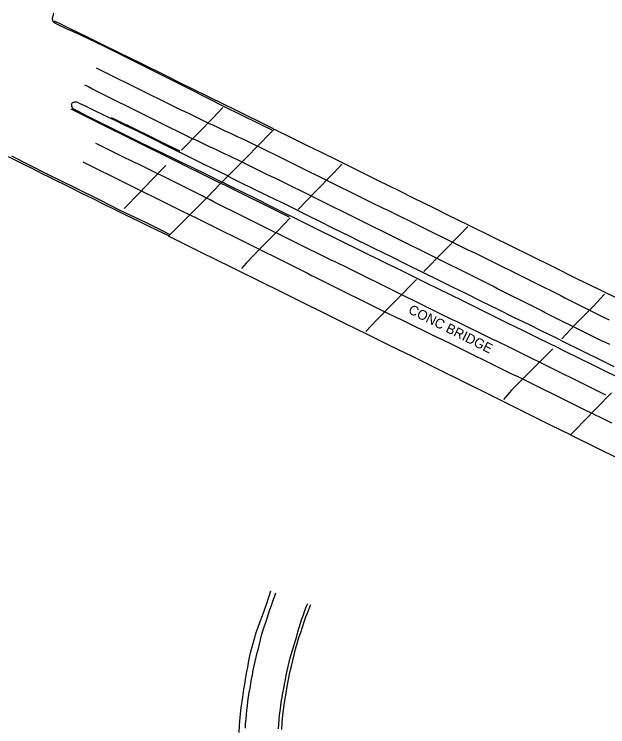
# Model space of a CAD drawing. Extents: x 1961683 to 1977751, y 798292 to 805767.
# Drawn here: x 1963000.6 to 1963330.2, y 799570.9 to 799966.6 of the extents above; entities that cross this region are included whole.
import ezdxf

# ---------------------------------------------------------------- set-up
doc = ezdxf.new("R2010")
doc.units = 0
for name, color, linetype in [('RD_EX_Bridge', 7, 'Continuous'), ('RD_EX_Bridge_Seam', 7, 'Continuous'), ('RD_EX_Conc', 7, 'Continuous'), ('RD_EX_Road', 7, 'Continuous'), ('RD_EX_Road_Paint', 7, 'Continuous'), ('RD_TX_RoadID', 7, 'Continuous')]:
    doc.layers.add(name, color=color, linetype=linetype)

msp = doc.modelspace()

# ---------------------------------------------------------------- linework, layer by layer
at = {"layer": 'RD_EX_Bridge'}
msp.add_lwpolyline([(1963332.27, 799756.44), (1963323.69, 799747.66), (1963317.32, 799741.08), (1963312.27, 799735.9), (1963309.4, 799732.97), (1963298.46, 799738.5), (1963282.11, 799746.62), (1963263.88, 799755.63), (1963250.13, 799762.41), (1963236.95, 799768.9), (1963222.78, 799775.95), (1963208.59, 799782.91), (1963196.82, 799788.73), (1963183.78, 799795.09), (1963172.38, 799800.78), (1963161.33, 799806.22), (1963149.22, 799812.21), (1963137.46, 799817.94), (1963121.48, 799825.98), (1963104.02, 799834.57), (1963086.31, 799843.33), (1963089.07, 799846.09), (1963098.17, 799855.18), (1963107.97, 799865.03), (1963114.7, 799872.23), (1963120.17, 799877.62), (1963129.42, 799886.96), (1963136.21, 799893.91), (1963143.07, 799900.86), (1963145, 799902.81), (1963154.36, 799898.23), (1963162.56, 799894.13), (1963170.65, 799890.17), (1963180.48, 799885.35), (1963191.19, 799879.95), (1963202.67, 799874.28), (1963214.45, 799868.55), (1963222.05, 799864.74), (1963233.51, 799859.13), (1963241.24, 799855.29), (1963252.64, 799849.67), (1963265.45, 799843.36), (1963276.64, 799837.85), (1963287.24, 799832.62), (1963300.11, 799826.32), (1963312.87, 799819.96), (1963325.6, 799813.75), (1963336.46, 799808.32)], dxfattribs=at)
at = {"layer": 'RD_EX_Bridge_Seam'}
for points in [[(1963158.28, 799858.15), (1963167.38, 799867.61), (1963178.01, 799878.63), (1963182.5, 799883.4)], [(1963153.87, 799853.49), (1963146.81, 799846.24), (1963137.2, 799836.5), (1963129.34, 799828.39), (1963126.78, 799825.34)], [(1963228.04, 799823.72), (1963238.72, 799834.71), (1963248.05, 799844.19), (1963252.46, 799848.75)], [(1963223.95, 799819.31), (1963212.48, 799807.62), (1963201.95, 799796.9), (1963195.93, 799790.51)], [(1963304.68, 799786.45), (1963311.96, 799794.09), (1963322.11, 799804.4), (1963328.44, 799811.09)], [(1963299.59, 799780.86), (1963286.57, 799767.73), (1963276.73, 799757.77), (1963272.28, 799752.71)]]:
    msp.add_lwpolyline(points, dxfattribs=at)
at = {"layer": 'RD_EX_Conc'}
for points in [[(1963119.13, 799876.82), (1963114.15, 799879.27), (1963106.16, 799883.21), (1963100.49, 799886.04), (1963095.38, 799888.57), (1963090.42, 799891), (1963084.86, 799893.77), (1963078.25, 799897.08), (1963073.87, 799899.24), (1963068.65, 799901.79), (1963062.6, 799904.72), (1963056.61, 799907.61), (1963051.55, 799910.05), (1963044.26, 799913.56), (1963039.79, 799915.71), (1963037.23, 799916.96), (1963035.86, 799917.58), (1963035.35, 799917.76), (1963034.96, 799917.85), (1963034.63, 799917.87), (1963034.29, 799917.85), (1963033.94, 799917.8), (1963033.59, 799917.7), (1963033.25, 799917.58), (1963032.96, 799917.44), (1963032.73, 799917.27), (1963032.54, 799917.09), (1963032.4, 799916.89), (1963032.33, 799916.68), (1963032.3, 799916.47), (1963032.33, 799916.25), (1963032.46, 799915.77), (1963032.62, 799915.25), (1963032.71, 799914.98), (1963032.84, 799914.75), (1963033.01, 799914.55), (1963033.2, 799914.37), (1963034.33, 799913.7), (1963036.84, 799912.36), (1963040.13, 799910.66), (1963043.57, 799908.93), (1963047.66, 799906.89), (1963052.9, 799904.27), (1963058.48, 799901.48), (1963063.62, 799898.95), (1963069.31, 799896.17), (1963076.54, 799892.63), (1963083.42, 799889.29), (1963088.04, 799887.09), (1963092.6, 799884.92), (1963099.28, 799881.68), (1963107.27, 799877.76), (1963115.75, 799873.58)], [(1963093.58, 799891.12), (1963103.07, 799900.87), (1963110.66, 799908.8), (1963116.49, 799914.89)], [(1963061.57, 799858.83), (1963070.28, 799867.67), (1963076.55, 799874.05), (1963084.73, 799882.55)], [(1963119.38, 799876.69), (1963121.88, 799875.43), (1963126.34, 799873.22), (1963132.75, 799870.08), (1963141.1, 799866.02), (1963145.77, 799863.74), (1963150.48, 799861.43), (1963155.22, 799859.08), (1963160, 799856.69), (1963164.73, 799854.32), (1963169.32, 799852.03), (1963178.11, 799847.65), (1963186.9, 799843.31), (1963191.5, 799841.05), (1963196.22, 799838.73), (1963200.94, 799836.42), (1963209.88, 799832.02), (1963218.29, 799827.85), (1963226.89, 799823.62), (1963235.68, 799819.33), (1963243.87, 799815.3), (1963251.55, 799811.5), (1963259.95, 799807.34), (1963264.49, 799805.09), (1963269.09, 799802.82), (1963277.9, 799798.48), (1963286.14, 799794.44), (1963293.41, 799790.87), (1963300, 799787.62), (1963308.03, 799783.64), (1963312.72, 799781.32), (1963317.49, 799778.97), (1963326.11, 799774.71), (1963333.52, 799771.06)], [(1963334.46, 799765.62), (1963328.66, 799768.46), (1963321.67, 799771.89), (1963313.68, 799775.83), (1963306.48, 799779.4), (1963301.84, 799781.68), (1963297.6, 799783.75), (1963291.58, 799786.7), (1963283.76, 799790.54), (1963279.16, 799792.81), (1963274.1, 799795.31), (1963268.61, 799798.02), (1963262.7, 799800.94), (1963256.37, 799804.07), (1963249.62, 799807.39), (1963242.83, 799810.74), (1963236.36, 799813.93), (1963230.22, 799816.96), (1963224.41, 799819.82), (1963218.78, 799822.59), (1963213.19, 799825.34), (1963207.64, 799828.06), (1963202.14, 799830.76), (1963196.48, 799833.55), (1963190.46, 799836.52), (1963184.08, 799839.68), (1963177.33, 799843.03), (1963170.88, 799846.23), (1963165.38, 799848.95), (1963157.24, 799852.97), (1963150.62, 799856.23), (1963143.22, 799859.92), (1963135.36, 799863.84), (1963127.34, 799867.84), (1963120.58, 799871.19), (1963116.52, 799873.2), (1963116.12, 799873.4)]]:
    msp.add_lwpolyline(points, dxfattribs=at)
at = {"layer": 'RD_EX_Road'}
for points in [[(1963022.38, 799967.3), (1963022.15, 799966.43), (1963021.96, 799965.64), (1963021.81, 799964.92), (1963021.74, 799964.38), (1963021.73, 799964.19), (1963021.74, 799964), (1963021.81, 799963.57), (1963021.93, 799963.07), (1963022, 799962.86), (1963022.09, 799962.69), (1963022.19, 799962.56), (1963022.38, 799962.42), (1963023.24, 799961.9), (1963024.55, 799961.2), (1963029.85, 799958.58), (1963032.94, 799957.16), (1963041, 799953.45), (1963050.5, 799948.9), (1963059.48, 799944.45), (1963068.35, 799940.02), (1963078.35, 799935.05), (1963088.66, 799929.83), (1963098.65, 799924.86), (1963107.81, 799920.27), (1963117.47, 799915.27), (1963125.89, 799911.14), (1963137.26, 799905.5), (1963143.63, 799902.39)], [(1963022.71, 799963), (1963023.11, 799962.84), (1963025.87, 799961.42), (1963030.66, 799959.11), (1963041.8, 799953.71), (1963049.3, 799949.96), (1963059.13, 799945.2), (1963070.89, 799939.38), (1963085.09, 799932.34), (1963092.31, 799928.7), (1963107.53, 799921.27), (1963117.83, 799916.23), (1963122, 799914.21), (1963144.45, 799903.09)], [(1962997.32, 799887.53), (1963001.34, 799885.57), (1963006.15, 799883.18), (1963011.05, 799880.71), (1963015.89, 799878.26), (1963020.27, 799876.06), (1963024.19, 799874.1), (1963028.11, 799872.18), (1963032.26, 799870.17), (1963037.69, 799867.51), (1963044.3, 799864.23), (1963050.44, 799861.15), (1963056.03, 799858.32), (1963062.37, 799855.23), (1963069.89, 799851.65), (1963074.62, 799849.37), (1963080.06, 799846.72), (1963086.22, 799843.69)], [(1963086.85, 799844.36), (1963082.23, 799846.78), (1963073.61, 799851.02), (1963059.03, 799857.89), (1963048.29, 799863.38), (1963034.5, 799870.2), (1963026.55, 799874.03), (1963018.86, 799877.88), (1963009.05, 799882.85), (1962999.21, 799887.76)], [(1963309.51, 799733.08), (1963336.93, 799719.62)], [(1963142.99, 799646.2), (1963142.2, 799643.88), (1963141.44, 799641.51), (1963140.72, 799639.24), (1963140.01, 799637.17), (1963139.26, 799635.2), (1963138.24, 799632.56), (1963136.98, 799629.25), (1963135.81, 799626.06), (1963134.78, 799623.03), (1963133.78, 799619.81), (1963132.84, 799616.46), (1963132.14, 799613.84), (1963131.67, 799611.88), (1963131.15, 799609.46), (1963130.57, 799606.54), (1963130.06, 799603.9), (1963129.65, 799601.62), (1963129.27, 799599.38), (1963128.9, 799597.1), (1963128.47, 799594.62), (1963127.95, 799591.73), (1963127.28, 799587.31), (1963126.5, 799581.49), (1963125.92, 799576.18), (1963125.57, 799571.68), (1963125.33, 799567.81)], [(1963149.12, 799569.41), (1963149.43, 799573.25), (1963149.84, 799577.42), (1963150.33, 799581.55), (1963150.9, 799585.59), (1963151.54, 799589.49), (1963152.24, 799593.34), (1963152.97, 799597.25), (1963153.73, 799601.03), (1963154.5, 799604.52), (1963155.27, 799607.78), (1963156.04, 799610.88), (1963156.85, 799613.99), (1963157.76, 799617.25), (1963158.72, 799620.43), (1963159.66, 799623.32), (1963160.63, 799626.17), (1963161.67, 799629.2), (1963162.61, 799631.9), (1963163.3, 799633.71), (1963164.01, 799635.48), (1963165.01, 799638.04), (1963165.34, 799638.85)]]:
    msp.add_lwpolyline(points, dxfattribs=at)
at = {"layer": 'RD_EX_Road_Paint'}
for points in [[(1963046.07, 799936.78), (1963048.31, 799935.67), (1963050.55, 799934.57), (1963052.8, 799933.46), (1963055.04, 799932.36), (1963057.28, 799931.25), (1963059.52, 799930.15), (1963061.76, 799929.04), (1963064.01, 799927.94), (1963066.25, 799926.83), (1963068.49, 799925.73), (1963070.73, 799924.62), (1963072.98, 799923.52), (1963075.22, 799922.42), (1963077.47, 799921.32), (1963079.71, 799920.22), (1963081.96, 799919.12), (1963084.2, 799918.02), (1963086.45, 799916.92), (1963088.69, 799915.82), (1963090.94, 799914.72), (1963093.18, 799913.62), (1963095.43, 799912.52), (1963097.67, 799911.42), (1963099.92, 799910.32), (1963102.16, 799909.22), (1963104.41, 799908.12), (1963106.66, 799907.04), (1963108.92, 799905.98), (1963111.19, 799904.93), (1963113.46, 799903.87), (1963115.72, 799902.81), (1963117.99, 799901.76), (1963120.25, 799900.7), (1963122.52, 799899.64), (1963124.78, 799898.58), (1963127.05, 799897.53), (1963129.31, 799896.47), (1963131.58, 799895.41), (1963133.82, 799894.31), (1963135.41, 799893.52)], [(1963126.76, 799884.62), (1963124.51, 799885.71), (1963122.26, 799886.81), (1963120.02, 799887.91), (1963117.77, 799889), (1963115.51, 799890.07), (1963113.25, 799891.13), (1963110.98, 799892.19), (1963108.72, 799893.26), (1963106.46, 799894.32), (1963104.2, 799895.38), (1963101.93, 799896.44), (1963099.67, 799897.51), (1963097.41, 799898.57), (1963095.14, 799899.63), (1963092.88, 799900.7), (1963090.63, 799901.79), (1963088.4, 799902.91), (1963086.16, 799904.03), (1963083.93, 799905.15), (1963081.69, 799906.27), (1963079.46, 799907.39), (1963077.22, 799908.5), (1963074.99, 799909.62), (1963072.75, 799910.74), (1963070.52, 799911.86), (1963068.28, 799912.98), (1963066.05, 799914.1), (1963063.81, 799915.22), (1963061.58, 799916.34), (1963059.34, 799917.46), (1963057.11, 799918.58), (1963054.87, 799919.7), (1963052.64, 799920.82), (1963050.4, 799921.94), (1963048.17, 799923.06), (1963045.93, 799924.18), (1963043.7, 799925.29), (1963041.46, 799926.41), (1963039.85, 799927.22)], [(1963115.01, 799872.87), (1963112.77, 799873.98), (1963110.53, 799875.09), (1963108.29, 799876.19), (1963106.04, 799877.3), (1963103.8, 799878.41), (1963101.56, 799879.51), (1963099.32, 799880.62), (1963097.08, 799881.73), (1963094.84, 799882.84), (1963092.6, 799883.94), (1963090.36, 799885.05), (1963088.11, 799886.16), (1963085.87, 799887.26), (1963083.63, 799888.37), (1963081.39, 799889.48), (1963079.15, 799890.58), (1963076.91, 799891.69), (1963074.67, 799892.8), (1963072.42, 799893.9), (1963070.18, 799895.01), (1963067.94, 799896.12), (1963065.7, 799897.23), (1963063.46, 799898.34), (1963061.22, 799899.45), (1963058.99, 799900.57), (1963056.75, 799901.68), (1963054.51, 799902.8), (1963052.27, 799903.91), (1963050.04, 799905.02), (1963047.8, 799906.14), (1963045.56, 799907.25), (1963043.32, 799908.37), (1963041.09, 799909.48), (1963038.85, 799910.6), (1963036.61, 799911.71), (1963034.37, 799912.82), (1963032.18, 799913.92)], [(1963054.53, 799909.33), (1963056.78, 799908.23), (1963059.02, 799907.13), (1963061.27, 799906.04), (1963063.51, 799904.94), (1963065.76, 799903.84), (1963068.01, 799902.74), (1963070.25, 799901.64), (1963072.5, 799900.55), (1963074.74, 799899.45), (1963076.99, 799898.35), (1963079.23, 799897.25), (1963081.48, 799896.15), (1963083.73, 799895.06), (1963085.97, 799893.96), (1963088.22, 799892.86), (1963090.46, 799891.76), (1963092.49, 799890.77)], [(1963107.28, 799864.56), (1963105.04, 799865.69), (1963102.81, 799866.81), (1963100.58, 799867.93), (1963098.34, 799869.05), (1963096.11, 799870.18), (1963093.87, 799871.3), (1963091.64, 799872.42), (1963089.41, 799873.54), (1963087.16, 799874.64), (1963084.92, 799875.75), (1963082.67, 799876.85), (1963080.43, 799877.95), (1963078.19, 799879.05), (1963075.94, 799880.16), (1963073.7, 799881.26), (1963071.46, 799882.36), (1963069.21, 799883.46), (1963066.97, 799884.56), (1963064.73, 799885.67), (1963062.48, 799886.77), (1963060.24, 799887.87), (1963057.99, 799888.97), (1963055.75, 799890.07), (1963053.51, 799891.18), (1963051.26, 799892.28), (1963049.02, 799893.38), (1963046.78, 799894.48), (1963045.97, 799894.88)], [(1963135.9, 799893.28), (1963138.14, 799892.17), (1963140.38, 799891.06), (1963142.62, 799889.95), (1963144.86, 799888.84), (1963147.1, 799887.73), (1963149.34, 799886.62), (1963151.58, 799885.51), (1963153.82, 799884.4), (1963156.06, 799883.29), (1963158.3, 799882.18), (1963160.54, 799881.07), (1963162.78, 799879.96), (1963165.02, 799878.85), (1963167.26, 799877.74), (1963169.5, 799876.63), (1963171.74, 799875.52), (1963173.98, 799874.41), (1963176.22, 799873.3), (1963178.47, 799872.2), (1963180.72, 799871.1), (1963182.96, 799870), (1963185.21, 799868.91), (1963187.45, 799867.81), (1963189.7, 799866.71), (1963191.94, 799865.61), (1963194.19, 799864.51), (1963196.43, 799863.41), (1963198.68, 799862.31), (1963200.93, 799861.21), (1963203.17, 799860.11), (1963205.42, 799859.02), (1963207.66, 799857.92), (1963209.91, 799856.82), (1963212.15, 799855.72), (1963214.4, 799854.62), (1963216.64, 799853.52), (1963218.89, 799852.42), (1963221.13, 799851.32), (1963223.38, 799850.21), (1963225.62, 799849.11), (1963227.86, 799848.01), (1963230.11, 799846.91), (1963232.35, 799845.8), (1963234.6, 799844.7), (1963236.84, 799843.6), (1963239.08, 799842.5), (1963241.33, 799841.4), (1963243.57, 799840.29), (1963245.81, 799839.19), (1963248.06, 799838.09), (1963250.3, 799836.98), (1963252.54, 799835.88), (1963254.79, 799834.78), (1963257.03, 799833.67), (1963259.27, 799832.57), (1963261.52, 799831.46), (1963263.76, 799830.36), (1963266, 799829.26), (1963268.24, 799828.15), (1963270.49, 799827.05), (1963272.73, 799825.94), (1963274.97, 799824.84), (1963277.22, 799823.74), (1963279.46, 799822.63), (1963281.7, 799821.53), (1963283.95, 799820.42), (1963286.19, 799819.32), (1963288.42, 799818.2), (1963290.65, 799817.07), (1963292.89, 799815.95), (1963295.12, 799814.83), (1963297.36, 799813.71), (1963299.59, 799812.59), (1963301.82, 799811.46), (1963304.06, 799810.34), (1963306.29, 799809.22), (1963308.53, 799808.1), (1963310.76, 799806.97), (1963312.99, 799805.85), (1963315.23, 799804.73), (1963317.46, 799803.61), (1963319.69, 799802.49), (1963321.93, 799801.36), (1963324.16, 799800.24), (1963326.4, 799799.12), (1963328.63, 799798), (1963330.87, 799796.88)], [(1963038.71, 799884.7), (1963040.95, 799883.58), (1963043.19, 799882.47), (1963045.43, 799881.36), (1963047.67, 799880.24), (1963049.9, 799879.13), (1963052.14, 799878.02), (1963054.38, 799876.9), (1963056.62, 799875.79), (1963058.86, 799874.67), (1963061.09, 799873.56), (1963063.33, 799872.45), (1963065.57, 799871.33), (1963067.81, 799870.22), (1963070.05, 799869.11), (1963072.29, 799867.99), (1963074.52, 799866.88), (1963076.76, 799865.77), (1963079, 799864.65), (1963081.24, 799863.54), (1963083.48, 799862.43), (1963085.72, 799861.33), (1963087.96, 799860.22), (1963090.2, 799859.11), (1963092.44, 799858), (1963094.68, 799856.89), (1963096.93, 799855.79), (1963097.79, 799855.36)], [(1963331.25, 799783.13), (1963329, 799784.24), (1963326.76, 799785.34), (1963324.52, 799786.45), (1963322.28, 799787.56), (1963320.04, 799788.67), (1963317.8, 799789.78), (1963315.56, 799790.89), (1963313.32, 799791.99), (1963311.08, 799793.1), (1963308.84, 799794.21), (1963306.6, 799795.32), (1963304.36, 799796.43), (1963302.12, 799797.54), (1963299.88, 799798.65), (1963297.64, 799799.76), (1963295.4, 799800.88), (1963293.17, 799802.01), (1963290.94, 799803.14), (1963288.71, 799804.26), (1963286.48, 799805.39), (1963284.25, 799806.52), (1963282.01, 799807.64), (1963279.78, 799808.77), (1963277.55, 799809.9), (1963275.32, 799811.02), (1963273.09, 799812.15), (1963270.86, 799813.28), (1963268.62, 799814.4), (1963266.39, 799815.53), (1963264.16, 799816.65), (1963261.92, 799817.77), (1963259.69, 799818.89), (1963257.45, 799820.01), (1963255.22, 799821.13), (1963252.98, 799822.25), (1963250.75, 799823.37), (1963248.51, 799824.49), (1963246.28, 799825.61), (1963244.04, 799826.73), (1963241.81, 799827.85), (1963239.57, 799828.97), (1963237.34, 799830.1), (1963235.1, 799831.21), (1963232.86, 799832.31), (1963230.62, 799833.42), (1963228.38, 799834.53), (1963226.13, 799835.64), (1963223.89, 799836.74), (1963221.65, 799837.85), (1963219.41, 799838.96), (1963217.17, 799840.06), (1963214.93, 799841.17), (1963212.68, 799842.28), (1963210.44, 799843.38), (1963208.2, 799844.49), (1963205.96, 799845.6), (1963203.72, 799846.71), (1963201.48, 799847.81), (1963199.24, 799848.92), (1963197, 799850.03), (1963194.76, 799851.15), (1963192.52, 799852.26), (1963190.28, 799853.37), (1963188.04, 799854.49), (1963185.8, 799855.6), (1963183.57, 799856.71), (1963181.33, 799857.82), (1963179.09, 799858.94), (1963176.85, 799860.05), (1963174.61, 799861.16), (1963172.37, 799862.28), (1963170.13, 799863.39), (1963167.9, 799864.5), (1963165.66, 799865.62), (1963163.42, 799866.73), (1963161.18, 799867.83), (1963158.93, 799868.93), (1963156.68, 799870.02), (1963154.44, 799871.12), (1963152.19, 799872.22), (1963149.94, 799873.31), (1963147.69, 799874.41), (1963145.45, 799875.5), (1963143.2, 799876.6), (1963140.95, 799877.7), (1963138.71, 799878.79), (1963136.46, 799879.89), (1963134.21, 799880.98), (1963131.97, 799882.08), (1963129.72, 799883.17), (1963127.47, 799884.27), (1963127.12, 799884.44)], [(1963153.34, 799853.9), (1963151.1, 799855.01), (1963148.86, 799856.12), (1963146.62, 799857.23), (1963144.38, 799858.34), (1963142.14, 799859.44), (1963139.9, 799860.55), (1963137.66, 799861.66), (1963135.42, 799862.77), (1963133.18, 799863.88), (1963130.94, 799864.99), (1963128.7, 799866.1), (1963126.46, 799867.21), (1963124.22, 799868.32), (1963121.98, 799869.43), (1963119.74, 799870.54), (1963117.5, 799871.64), (1963115.39, 799872.68)], [(1963329.19, 799755.16), (1963326.95, 799756.27), (1963324.71, 799757.38), (1963322.47, 799758.5), (1963320.23, 799759.61), (1963317.99, 799760.72), (1963315.76, 799761.83), (1963313.51, 799762.94), (1963311.27, 799764.04), (1963309.03, 799765.14), (1963306.78, 799766.25), (1963304.54, 799767.35), (1963302.29, 799768.45), (1963300.05, 799769.55), (1963297.81, 799770.66), (1963295.56, 799771.76), (1963293.32, 799772.86), (1963291.08, 799773.97), (1963288.83, 799775.07), (1963286.59, 799776.17), (1963284.35, 799777.27), (1963282.1, 799778.38), (1963279.86, 799779.48), (1963277.62, 799780.58), (1963275.37, 799781.69), (1963273.13, 799782.79), (1963270.88, 799783.89), (1963268.64, 799784.98), (1963266.39, 799786.07), (1963264.14, 799787.16), (1963261.89, 799788.26), (1963259.64, 799789.35), (1963257.39, 799790.44), (1963255.14, 799791.53), (1963252.9, 799792.63), (1963250.65, 799793.72), (1963248.4, 799794.81), (1963246.15, 799795.91), (1963243.9, 799797), (1963241.65, 799798.09), (1963239.4, 799799.18), (1963237.16, 799800.28), (1963234.91, 799801.37), (1963232.67, 799802.48), (1963230.43, 799803.6), (1963228.19, 799804.71), (1963225.95, 799805.82), (1963223.71, 799806.93), (1963221.48, 799808.04), (1963219.24, 799809.16), (1963217, 799810.27), (1963214.76, 799811.38), (1963212.52, 799812.49), (1963210.28, 799813.6), (1963208.04, 799814.72), (1963205.8, 799815.83), (1963203.56, 799816.94), (1963201.32, 799818.05), (1963199.08, 799819.16), (1963196.84, 799820.27), (1963194.6, 799821.37), (1963192.35, 799822.46), (1963190.1, 799823.56), (1963187.86, 799824.66), (1963185.61, 799825.76), (1963183.36, 799826.85), (1963181.12, 799827.95), (1963178.87, 799829.05), (1963176.62, 799830.14), (1963174.38, 799831.24), (1963172.13, 799832.34), (1963169.89, 799833.43), (1963167.64, 799834.53), (1963165.39, 799835.63), (1963163.15, 799836.73), (1963160.9, 799837.83), (1963158.66, 799838.94), (1963156.42, 799840.05), (1963154.18, 799841.16), (1963151.94, 799842.27), (1963149.7, 799843.38), (1963147.46, 799844.49), (1963145.22, 799845.6), (1963142.98, 799846.71), (1963140.75, 799847.82), (1963138.51, 799848.94), (1963136.27, 799850.05), (1963134.03, 799851.16), (1963131.79, 799852.27), (1963129.55, 799853.38), (1963127.31, 799854.49), (1963125.08, 799855.62), (1963122.84, 799856.74), (1963120.61, 799857.86), (1963118.37, 799858.98), (1963116.14, 799860.11), (1963113.91, 799861.23), (1963111.67, 799862.35), (1963109.44, 799863.48), (1963107.62, 799864.39)], [(1963098.58, 799854.96), (1963100.83, 799853.86), (1963103.07, 799852.75), (1963105.31, 799851.64), (1963107.55, 799850.53), (1963109.79, 799849.42), (1963112.03, 799848.32), (1963114.27, 799847.21), (1963116.51, 799846.1), (1963118.75, 799844.99), (1963120.99, 799843.88), (1963123.23, 799842.78), (1963125.48, 799841.67), (1963127.72, 799840.56), (1963129.96, 799839.45), (1963132.2, 799838.34), (1963134.44, 799837.23), (1963136.68, 799836.13), (1963138.92, 799835.01), (1963141.15, 799833.89), (1963143.39, 799832.78), (1963145.63, 799831.66), (1963147.87, 799830.55), (1963150.1, 799829.43), (1963152.34, 799828.31), (1963154.58, 799827.2), (1963156.81, 799826.08), (1963159.05, 799824.97), (1963161.29, 799823.85), (1963163.53, 799822.74), (1963165.76, 799821.62), (1963168, 799820.5), (1963170.24, 799819.39), (1963172.47, 799818.27), (1963174.71, 799817.16), (1963176.95, 799816.04), (1963179.19, 799814.94), (1963181.43, 799813.83), (1963183.67, 799812.72), (1963185.91, 799811.61), (1963188.15, 799810.5), (1963190.39, 799809.39), (1963192.63, 799808.28), (1963194.87, 799807.17), (1963197.11, 799806.06), (1963199.35, 799804.95), (1963201.6, 799803.84), (1963203.84, 799802.73), (1963206.08, 799801.62), (1963208.32, 799800.52), (1963210.56, 799799.41), (1963212.8, 799798.3), (1963215.05, 799797.21), (1963217.3, 799796.11), (1963219.54, 799795.02), (1963221.79, 799793.93), (1963224.04, 799792.84), (1963226.29, 799791.74), (1963228.54, 799790.65), (1963230.79, 799789.56), (1963233.04, 799788.46), (1963235.28, 799787.37), (1963237.53, 799786.28), (1963239.78, 799785.19), (1963242.03, 799784.09), (1963244.28, 799783), (1963246.53, 799781.91), (1963248.78, 799780.82), (1963251.02, 799779.72), (1963253.27, 799778.62), (1963255.51, 799777.51), (1963257.75, 799776.41), (1963259.99, 799775.3), (1963262.24, 799774.2), (1963264.48, 799773.09), (1963266.72, 799771.99), (1963268.96, 799770.88), (1963271.21, 799769.78), (1963273.45, 799768.67), (1963275.69, 799767.57), (1963277.93, 799766.46), (1963280.18, 799765.36), (1963282.42, 799764.25), (1963284.66, 799763.15), (1963286.9, 799762.04), (1963289.14, 799760.93), (1963291.38, 799759.82), (1963293.62, 799758.71), (1963295.86, 799757.6), (1963298.1, 799756.49), (1963300.34, 799755.39), (1963302.58, 799754.28), (1963304.82, 799753.17), (1963307.06, 799752.06), (1963309.3, 799750.95), (1963311.54, 799749.84), (1963313.79, 799748.73), (1963316.03, 799747.62), (1963318.27, 799746.51), (1963320.51, 799745.41), (1963320.78, 799745.27)], [(1963332.4, 799739.54), (1963330.16, 799740.65), (1963327.92, 799741.75), (1963325.68, 799742.86), (1963323.43, 799743.97), (1963321.61, 799744.87)], [(1963128.96, 799570.09), (1963129.12, 799572.59), (1963129.31, 799575.08), (1963129.53, 799577.57), (1963129.79, 799580.06), (1963130.08, 799582.54), (1963130.41, 799585.02), (1963130.78, 799587.49), (1963131.15, 799589.96), (1963131.53, 799592.43), (1963131.94, 799594.9), (1963132.39, 799597.35), (1963132.86, 799599.81), (1963133.33, 799602.27), (1963133.84, 799604.71), (1963134.39, 799607.15), (1963134.96, 799609.59), (1963135.56, 799612.01), (1963136.16, 799614.44), (1963136.78, 799616.86), (1963137.36, 799619.29), (1963137.92, 799621.73), (1963138.59, 799624.13), (1963139.43, 799626.48), (1963140.24, 799628.85), (1963141.02, 799631.22), (1963141.8, 799633.59), (1963142.61, 799635.96), (1963143.43, 799638.32), (1963144.27, 799640.68), (1963145.12, 799643.03), (1963145.94, 799645.23)], [(1963147.3, 799569.86), (1963147.5, 799572.35), (1963147.68, 799574.85), (1963147.98, 799577.33), (1963148.34, 799579.8), (1963148.61, 799582.28), (1963148.89, 799584.77), (1963149.36, 799587.22), (1963149.83, 799589.68), (1963150.24, 799592.14), (1963150.66, 799594.61), (1963151.17, 799597.05), (1963151.68, 799599.5), (1963152.22, 799601.94), (1963152.77, 799604.38), (1963153.31, 799606.82), (1963153.86, 799609.26), (1963154.58, 799611.65), (1963155.3, 799614.05), (1963156.01, 799616.44), (1963156.73, 799618.84), (1963157.44, 799621.23), (1963158.16, 799623.62), (1963158.87, 799626.02), (1963159.59, 799628.41), (1963160.39, 799630.78), (1963161.19, 799633.15), (1963162.06, 799635.49), (1963162.97, 799637.81), (1963163.62, 799639.42)]]:
    msp.add_lwpolyline(points, dxfattribs=at)

# ---------------------------------------------------------------- texts
at = {"layer": 'RD_TX_RoadID'}
msp.add_text('CONC BRIDGE', height=5.4, rotation=333.4525, dxfattribs=at).set_placement((1963218.95, 799800.82))

doc.saveas('drawing.dxf')
